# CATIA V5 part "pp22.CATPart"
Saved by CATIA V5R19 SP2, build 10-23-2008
Part number: pp22
Bounding box of the stored display mesh (mm): x -20 to 20, y -241.324 to -172.014, z -77.381 to 77.381
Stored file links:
  D:\thinkmotion-MPB\Dropbox\Pack 1 sylvain\jlicbarski\thk2\pp22.CATPart
  D:\thinkmotion-MPB\Dropbox\Pack 1 sylvain\jlicbarski\thk2\Brasmeca.CATProduct
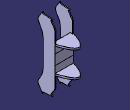
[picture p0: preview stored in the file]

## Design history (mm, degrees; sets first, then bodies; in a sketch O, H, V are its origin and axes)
External parameters (linked from other documents)
  External.Length.2 = 15.677 mm
  External.Length.1 = 25.952 mm
  External.Length.4 = 11.712 mm
  External.Length.3 = 10.679 mm
  External.poche1 = 21 mm
  External.Length.5 = 32.353 mm
AxisSystem1: origin (0, 0, 0), X (1, 0, 0), Y (0, 1, 0), Z (0, 0, 1)
Set1
  Plane1: linked copy from another document
Body1 (main body)
  Plane2: type Offset, RefPlane YZ plane of AxisSystem1, Offset 20
  Sketch1 on Plane2, origin (20, 0, 0), H (0, 1, 0), V (0, 0, 1)
    line L1 (-204.323, 10.9505) -> (-204.323, 51.8288)
    line L2 (-230.275, 10.9505) -> (-230.275, 24.6131)
    reference projected line E1 (-220, 90) -> (-220, -90) from Sketch2.L10
    line L3 (-206.3384, 58.3975) -> (-213.9948, 69.6997)
    line L4 (-213.9948, 69.6997) -> (-210.2722, 72.2214)
    line L5 (-210.2722, 72.2214) -> (-231.7363, 74.1152)
    line L6 (-231.7363, 74.1152) -> (-231.7363, 77.3807)
    line L7 (-231.7363, 77.3807) -> (-239.6326, 65.0815)
    line L8 (-239.9028, 53.9869) -> (-236.5773, 48.2064)
    arc A1 centre (-216.035, 51.8288) radius 11.712 from (-204.323, 51.8288) to (-206.3384, 58.3975) ccw
    arc A2 centre (-277.5883, 24.6131) radius 47.3133 from (-230.275, 24.6131) to (-236.5773, 48.2064) ccw
    arc A3 centre (-230.6462, 59.3121) radius 10.679 from (-239.6326, 65.0815) to (-239.9028, 53.9869) ccw
    line L9 (-204.323, -10.9505) -> (-204.323, -51.8288)
    arc A4 centre (-216.035, -51.8288) radius 11.712 from (-204.323, -51.8288) to (-206.3384, -58.3975) cw
    line L10 (-206.3384, -58.3975) -> (-213.9948, -69.6997)
    line L11 (-213.9948, -69.6997) -> (-210.2722, -72.2214)
    line L12 (-210.2722, -72.2214) -> (-231.7363, -74.1152)
    line L13 (-231.7363, -77.3807) -> (-239.6326, -65.0815)
    line L14 (-231.7363, -74.1152) -> (-231.7363, -77.3807)
    arc A5 centre (-230.6462, -59.3121) radius 10.679 from (-239.6326, -65.0815) to (-239.9028, -53.9869) cw
    line L15 (-239.9028, -53.9869) -> (-236.5773, -48.2064)
    arc A6 centre (-277.5883, -24.6131) radius 47.3133 from (-230.275, -24.6131) to (-236.5773, -48.2064) cw
    line L16 (-230.275, -10.9505) -> (-230.275, -24.6131)
    line L17 (-204.323, 10.9505) -> (-204.323, -10.9505)
    line L18 (-230.275, 10.9505) -> (-230.275, -10.9505)
    distance L1 E1 = 15.677 {= External.Length.2}
    distance L2 L1 = 25.952 {= External.Length.1}
    radius A1 = 11.712 {= External.Length.4}
    radius A3 = 10.679 {= External.Length.3}
    distance L9 E1 = 15.677
    distance L16 L9 = 25.952
    radius A5 = 10.679
    radius A4 = 11.712
  Sketch2 on Plane1, origin (0, -220, 0), H (-1, 0, 0), V (0, 0, 1)
    line L1 (-18, 90) -> (-18, 30)
    line L2 (-18, 30) -> (18, 30)
    line L3 (18, 30) -> (18, 90)
    line L4 (18, 90) -> (20, 90)
    line L5 (20, 90) -> (20, -90)
    line L6 (20, -90) -> (18, -90)
    line L7 (18, -90) -> (18, -30)
    line L8 (18, -30) -> (-18, -30)
    line L9 (-18, -30) -> (-18, -90)
    line L10 (-20, 90) -> (-20, -90)
    line L11 (-18, -90) -> (-20, -90)
    line L12 (-18, 90) -> (-20, 90)
    distance L5 L10 = 40
    distance L5 V = 20
    distance L3 L5 = 2
    distance L1 L10 = 2
    distance L5 L7 = 2
    distance L9 L10 = 2
    distance L2 H = 30
    distance H L8 = 30
    distance L4 L2 = 60
    distance L12 L2 = 60
    distance L6 L8 = 60
    distance L8 L11 = 60
  SolidCombine1: FirstComponentDirection Sketch1, FirstComponentProfile Sketch1, SecondComponentDirection Sketch2, SecondComponentProfile Sketch2
  Sketch3 on face of SolidCombine1 from Sketch1.L18, origin (0, -230.275, 0), H (1, 0, 0), V (0, 0, 1)
    line L1 (-18, 30) -> (18, 30)
    line L2 (18, 30) -> (18, -30)
    line L3 (18, -30) -> (-18, -30)
    line L4 (-18, -30) -> (-18, 30)
    distance L2 V = 18
    distance L2 L4 = 36
    distance L1 H = 30
    distance L1 L3 = 60
  Pocket1: profile Sketch3, direction (0, 1, 0), length 21 {= External.poche1}
  Sketch4 on start face of Pocket1, origin (0, -230.275, 0), H (-1, 0, 0), V (0, 0, 1)
    line L1 (-18, 32.6757) -> (18, 32.6757)
    line L2 (18, 32.6757) -> (18, 24.2838)
    line L3 (18, 24.2838) -> (-18, 24.2838)
    line L4 (-18, 24.2838) -> (-18, 32.6757)
    distance L2 V = 18
    distance L2 L4 = 36
  Pocket2: profile Sketch4, direction (0, -1, 0), length 5
  Sketch5 on start face of Pocket1, origin (0, -230.275, 0), H (-1, 0, 0), V (0, 0, 1)
    line L1 (-18, -24.1838) -> (18, -24.1838)
    line L2 (18, -24.1838) -> (18, -31.1689)
    line L3 (18, -31.1689) -> (-18, -31.1689)
    line L4 (-18, -31.1689) -> (-18, -24.1838)
    distance L2 V = 18
    distance L2 L4 = 36
  Pocket3: profile Sketch5, direction (0, -1, 0), length 5
  Sketch6 on face of SolidCombine1 from Sketch1.L9, origin (0, -204.323, 0), H (-1, 0, 0), V (0, 0, 1)
  Sketch7 on face of SolidCombine1 from Sketch2.L2, origin (0, 0, 30), H (1, 0, 0), V (0, 1, 0)
    spline S1 through (20.0794, -204.3669) (0, -172.0139) (-19.9505, -204.3668)
    line L1 (-19.9505, -204.3668) -> (20.0794, -204.3669)
    point P1 (-19.9505, -204.3668)
    point P2 (20.0794, -204.3669)
    point P3 (-19.9505, -204.3668)
    point P4 (20.0794, -204.3669)
    point P5 (0, -172.0139)
    distance P5 L1 = 32.353 {= External.Length.5}
    coincidence: P3 P1, P4 P2
  Sketch8 on face of SolidCombine1 from Sketch1.L1, origin (0, -204.323, 0), H (-1, 0, 0), V (0, 0, 1)
    line L1 (-20, 30) -> (20, 30)
    line L2 (20, 30) -> (20, 26)
    line L3 (20, 26) -> (-20, 26)
    line L4 (-20, 26) -> (-20, 30)
    distance L1 H = 30
    distance L3 H = 26
    distance L2 V = 20
    distance L2 L4 = 40
  SolidCombine2: FirstComponentDirection Sketch7, FirstComponentProfile Sketch7, SecondComponentDirection Sketch8, SecondComponentProfile Sketch8
  Mirror1: of SolidCombine2, about XY plane of AxisSystem1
